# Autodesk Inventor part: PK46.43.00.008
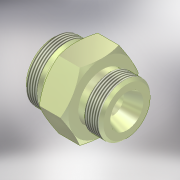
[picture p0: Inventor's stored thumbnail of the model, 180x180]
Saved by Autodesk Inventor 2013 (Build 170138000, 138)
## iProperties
Shininess: 64.0
Length Units: 11269
Angle Units: 11279
Time Units: 11290
Mass Units: 11283
Length Display Precision: 3
Angle Display Precision: 2
Compacted: True
Created: 2002-12
Part Number: PK46.43.00.008
Document SubType Name: Modeling
Designer: GSasha
Material: Steel, Mild
Density: 7.86 g/cm^3
Density: 0.0
Volumn: 0.0
Area: 0.0
PropertySet Name: Model Information
Control State: 0
Master: False
Checked Out: True
Checked Out Date: 2008-10-09
Last Check In Date: 2008-10-09
Author: GSasha
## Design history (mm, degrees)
sketch "Sketch1"
  geometry: L1 (-19.251, 0)-(-19.251, 22); L2 (-19.251, 22)-(-17.251, 24); L3 (-17.251, 24)-(-8.398, 24); L4 (-8.398, 24)-(-6.398, 22); L5 (-6.044, 21.854)-(-2.251, 21.854); L6 (-1.251, 22.854)-(-1.251, 27.5); L7 (-1.251, 27.5)-(2.708, 34.358); L8 (2.708, 34.358)-(16.789, 34.358); L9 (16.789, 34.358)-(20.749, 27.5); L10 (20.749, 27.5)-(20.749, 19.5); L11 (40.749, 19)-(40.749, 0); L12 (40.749, 0)-(-19.251, 0) reference; L13 (-19.251, 9.5)-(28.794, 9.5); L14 (28.794, 9.5)-(40.749, 13.5); L15 (40.749, 19)-(38.749, 21); L16 (38.749, 21)-(27.249, 21); L17 (27.249, 21)-(25.749, 19.5); L18 (25.749, 19.5)-(20.749, 19.5); A1 r 0.5 centre (-6.044, 22.354) between (-6.398, 22) and (-6.044, 21.854); A2 r 1 centre (-2.251, 22.854) between (-2.251, 21.854) and (-1.251, 22.854); 2 further points
  constraints: 36 end point, 9 parallel, 6 point on line, 4 perpendicular, 4 point on circle, 4 tangent, 2 centre point, 2 equal length, 1 horizontal, 1 vertical
  dimensions: "d0" = 2 distance from line of L2.end L1; "d1" = 45 deg angle of L1 L2; "d4" = 5 distance of point (-6.251, 21.854) point (-1.251, 21.854); "d6" = 30 deg angle of L7 L6; "d7" = 30 deg angle of L9 L10; "d9" = 18 distance between parallel lines of L1 L6; "d10" = 60 distance of L11.end L1.start; "d11" = 20 distance between parallel lines of L11 L10; "d12" = 9.5 distance between parallel lines of L12 L13; "d13" = 24 distance between parallel lines of L12 L3; "d14" = 27.5 distance from line of L6.end L12; "d15" = 18.5 deg angle of L14 L12; "d16" = 13.5 distance from line of L14.end L12; "d17" = 0.5 radius of A1; "d18" = 1 radius of A2; "d23" = 45 deg angle of L16 L15 (derived); "d24" = 2 horizontal distance of L11.start L15.end; "d25" = 135 deg angle of L16 L17 (derived); "d26" = 5 distance of L17.end L10.end; "d27" = 21 distance between parallel lines of L16 L12; "d28" = 19.5 distance between parallel lines of L12 L18
revolve "Revolution1" sketch "Sketch1" stored, may be unused: angle "d19" = 90 deg
sketch "Sketch2"
  geometry: L1 (0, 31.754)-(27.5, 15.877); L2 (27.5, 15.877)-(27.5, -15.877); L3 (27.5, -15.877)-(0, -31.754); L4 (0, -31.754)-(-27.5, -15.877); L5 (-27.5, -15.877)-(-27.5, 15.877); L6 (-27.5, 15.877)-(0, 31.754); C1 r 34.358 at (0, 0) reference; 1 further point
  constraints: 12 end point, 1 coincident, 11 other
  dimensions: "d20" = 55 distance between parallel lines of L2 L5
extrude "Extrusion1" cut sketch "Sketch2" stored distance "d21" = 10; taper "d22" = 0 deg
feature "Резьба1" dims "d29" = 10, "d30" = 0
feature "Резьба2" dims "d31" = 10, "d32" = 0
body "Solid1"
